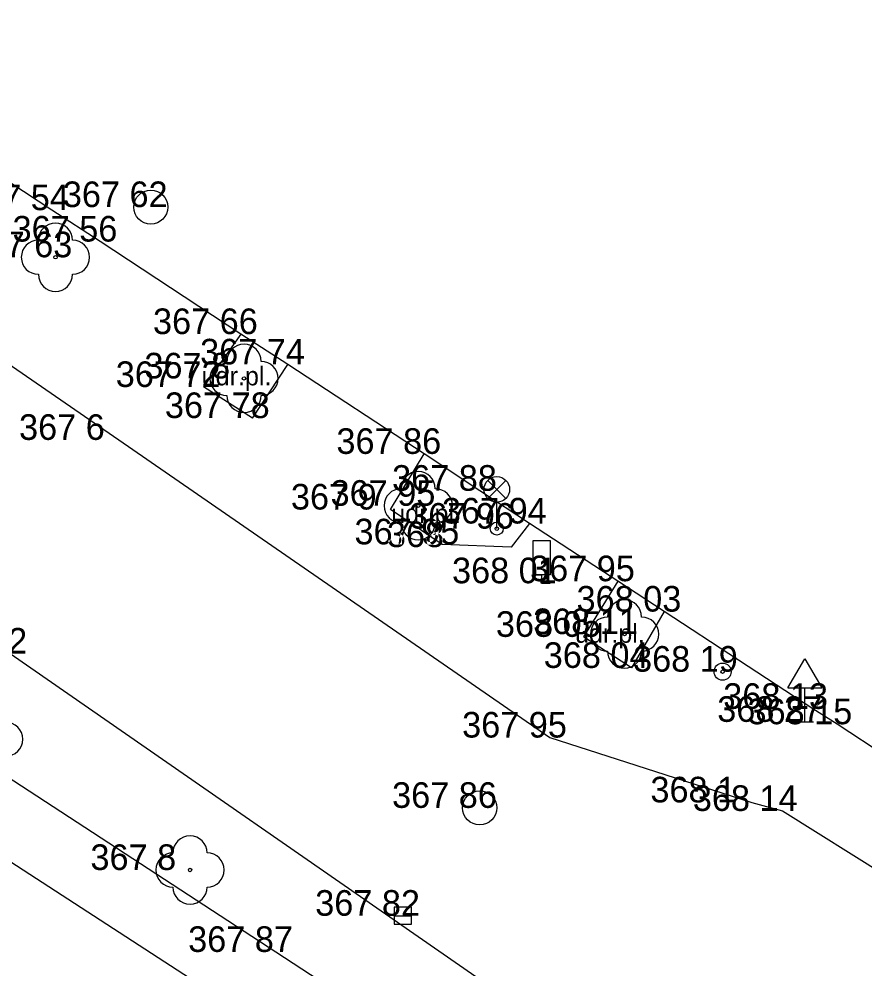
# Model space of a CAD drawing. Extents: x -688316 to -688024, y -973785 to -973591.
# Drawn here: x -688150.19 to -688125.42, y -973669.95 to -973642.12 of the extents above; entities that cross this region are included whole.
import ezdxf

# ---------------------------------------------------------------- set-up
doc = ezdxf.new("R2010")
doc.units = 0
for name, color, linetype in [('Default', 7, 'Continuous'), ('Vrstva 10', 7, 'Continuous'), ('Vrstva 22', 7, 'Continuous'), ('Vrstva 25', 7, 'Continuous'), ('Vrstva 27', 7, 'Continuous'), ('Vrstva 3', 7, 'Continuous'), ('Vrstva 33', 7, 'Continuous'), ('Vrstva 34', 7, 'Continuous'), ('Vrstva 40', 7, 'Continuous'), ('Vrstva 58', 7, 'Continuous')]:
    doc.layers.add(name, color=color, linetype=linetype)

# ---------------------------------------------------------------- blocks, each defined once
blk = doc.blocks.new('DZ')
at = {"layer": 'Vrstva 34'}
for p, q in [((-5, 10), (0, 18.5)), ((0, 18.5), (5, 10)), ((-5, 10), (5, 10)), ((0, 0), (0, 10)), ((-2.49, 0), (2.49, 0))]:
    blk.add_line(p, q, dxfattribs=at)
blk = doc.blocks.new('POINT_DISPLAY')
at = {"layer": 'Default'}
blk.add_line((0, 0), (0, 0), dxfattribs=at)
blk = doc.blocks.new('SKRIN')
at = {"layer": 'Vrstva 58'}
for p, q in [((-2.5, 2.5), (-2.5, 12.5)), ((-2.5, 12.5), (2.5, 12.5)), ((2.5, 12.5), (2.5, 2.5)), ((2.5, 2.5), (-2.5, 2.5)), ((-2.5, 2.5), (0, 2.5)), ((0, 2.5), (0, 0)), ((0, 0), (2.5, 0))]:
    blk.add_line(p, q, dxfattribs=at)
blk.add_blockref('POINT_DISPLAY', (2.5, 2.5), dxfattribs=at)
blk = doc.blocks.new('SAK')
at = {"layer": 'Vrstva 27'}
blk.add_circle((0, 0), 5, dxfattribs=at)
blk = doc.blocks.new('STL')
at = {"layer": 'Vrstva 22'}
blk.add_circle((0, 0), 0.5, dxfattribs=at)
for centre, start, end in [((0, 5), 0, 180), ((-5, 0), 90, 270), ((5, 0), 270, 90), ((0, -5), 180, 0)]:
    blk.add_arc(centre, 5, start, end, dxfattribs=at)
blk = doc.blocks.new('ZKUDR0')
at = {"layer": 'Vrstva 40'}
blk.add_text('udr.pl.', height=5.5, dxfattribs=at).set_placement((-11.71, -3.04))
blk = doc.blocks.new('LA')
at = {"layer": 'Vrstva 33'}
for p, q in [((-2.65, 14.15), (2.65, 8.85)), ((-2.65, 8.85), (2.65, 14.15)), ((0, 0), (0, 7.75))]:
    blk.add_line(p, q, dxfattribs=at)
for centre, radius in [((0, 11.5), 3.75), ((0, 0), 1.9), ((0, 0), 0.5)]:
    blk.add_circle(centre, radius, dxfattribs=at)
blk = doc.blocks.new('VP')
at = {"layer": 'Vrstva 27'}
blk.add_line((-2.5, 0), (2.5, 0), dxfattribs=at)
blk.add_lwpolyline([(-2.5, -2.5), (2.5, -2.5), (2.5, 2.5), (-2.5, 2.5)], close=True, dxfattribs=at)
blk = doc.blocks.new('SPMR')
at = {"layer": 'Vrstva 25'}
for radius in [2.5, 0.5]:
    blk.add_circle((0, 0), radius, dxfattribs=at)

msp = doc.modelspace()

# ---------------------------------------------------------------- linework, layer by layer
at = {"layer": 'Vrstva 10'}
for p, q in [((-688165.13, -973642.12), (-688147.27, -973654.45)), ((-688143.69, -973651.35), (-688144.79, -973652.9)), ((-688143.35, -973653.81), (-688142.32, -973652.24)), ((-688143.35, -973653.81), (-688144.79, -973652.9)), ((-688147.27, -973654.45), (-688134.65, -973663.17)), ((-688139.31, -973656.49), (-688138.33, -973654.86)), ((-688135.24, -973656.9), (-688135.78, -973657.59)), ((-688132.66, -973658.59), (-688133.66, -973660.22)), ((-688131.3, -973659.48), (-688132.26, -973661.13)), ((-688132.26, -973661.13), (-688133.66, -973660.22)), ((-688150.45, -973660.71), (-688131.07, -973674.15)), ((-688126.24, -973662.78), (-688126.95, -973662.33)), ((-688119.64, -973667.13), (-688126.24, -973662.78)), ((-688152.2, -973663.22), (-688142.67, -973669.45)), ((-688134.65, -973663.17), (-688128.73, -973665.07)), ((-688128.73, -973665.07), (-688127.84, -973665.32)), ((-688152.48, -973665.48), (-688142.05, -973672.25)), ((-688127.84, -973665.32), (-688121.4, -973669.35))]:
    msp.add_line(p, q, dxfattribs=at)
for points in [[(-688149.23, -973647.72), (-688153.35, -973645.01), (-688154.77, -973644.07)], [(-688143.69, -973651.35), (-688147.81, -973648.64), (-688149.23, -973647.72)], [(-688138.33, -973654.86), (-688142.32, -973652.24), (-688143.69, -973651.35)], [(-688132.66, -973658.59), (-688135.24, -973656.9), (-688136.7, -973655.94), (-688138.33, -973654.86)], [(-688135.78, -973657.59), (-688137.8, -973657.51), (-688139.31, -973656.49)], [(-688126.95, -973662.33), (-688131.3, -973659.48), (-688132.66, -973658.59)], [(-688142.67, -973669.45), (-688132.43, -973676.15), (-688129.37, -973678.25)]]:
    msp.add_lwpolyline(points, dxfattribs=at)

# ---------------------------------------------------------------- block references
at = {"layer": 'Vrstva 22', "xscale": 0.1, "yscale": 0.10000000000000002}
for p in [(-688149.12, -973649.1), (-688143.6, -973652.65), (-688138.5, -973656.38), (-688132.46, -973660.14), (-688151.08, -973663.22), (-688145.18, -973667.05)]:
    msp.add_blockref('STL', p, dxfattribs=at)
at = {"layer": 'Vrstva 25', "xscale": 0.1, "yscale": 0.10000000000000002}
msp.add_blockref('SPMR', (-688129.59, -973661.24), dxfattribs=at)
at = {"layer": 'Vrstva 27', "xscale": 0.1, "yscale": 0.10000000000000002}
for name, p in [('SAK', (-688146.33, -973647.63)), ('SAK', (-688136.7, -973665.23)), ('VP', (-688138.95, -973668.39))]:
    msp.add_blockref(name, p, dxfattribs=at)
at = {"layer": 'Vrstva 33', "xscale": 0.1, "yscale": 0.10000000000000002}
msp.add_blockref('LA', (-688136.2, -973657.05), dxfattribs=at)
at = {"layer": 'Vrstva 34', "xscale": 0.1, "yscale": 0.10000000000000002}
msp.add_blockref('DZ', (-688127.18, -973662.71), dxfattribs=at)
msp.add_blockref('DZ', (-688127.18, -973662.71), dxfattribs=at)
msp.add_blockref('DZ', (-688127.18, -973662.71), dxfattribs=at)
msp.add_blockref('DZ', (-688127.18, -973662.71), dxfattribs=at)
at = {"layer": 'Vrstva 40', "xscale": 0.1, "yscale": 0.10000000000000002}
for p in [(-688143.67, -973652.55), (-688138.12, -973656.58), (-688132.74, -973660.09)]:
    msp.add_blockref('ZKUDR0', p, dxfattribs=at)
at = {"layer": 'Vrstva 58', "xscale": 0.1, "yscale": 0.10000000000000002}
msp.add_blockref('SKRIN', (-688134.89, -973658.65), dxfattribs=at)
msp.add_blockref('SKRIN', (-688134.89, -973658.65), dxfattribs=at)
msp.add_blockref('SKRIN', (-688134.89, -973658.65), dxfattribs=at)
msp.add_blockref('SKRIN', (-688134.89, -973658.65), dxfattribs=at)

# ---------------------------------------------------------------- texts
at = {"layer": 'Vrstva 3'}
for s, p in [('367 54 ', (-688151.796, -973647.72)), ('367 54 ', (-688151.796, -973647.72)), ('367 54 ', (-688151.796, -973647.72)), ('367 54 ', (-688151.796, -973647.72)), ('367 54 ', (-688151.796, -973647.72)), ('367 54 ', (-688151.796, -973647.72)), ('367 54 ', (-688151.796, -973647.72)), ('367 62 ', (-688148.905, -973647.63)), ('367 62 ', (-688148.905, -973647.63)), ('367 62 ', (-688148.905, -973647.63)), ('367 62 ', (-688148.905, -973647.63)), ('367 62 ', (-688148.905, -973647.63)), ('367 62 ', (-688148.905, -973647.63)), ('367 62 ', (-688148.905, -973647.63)), ('367 56 ', (-688150.376, -973648.64)), ('367 56 ', (-688150.376, -973648.64)), ('367 56 ', (-688150.376, -973648.64)), ('367 56 ', (-688150.376, -973648.64)), ('367 56 ', (-688150.376, -973648.64)), ('367 56 ', (-688150.376, -973648.64)), ('367 56 ', (-688150.376, -973648.64)), ('367 63 ', (-688151.695, -973649.1)), ('367 63 ', (-688151.695, -973649.1)), ('367 63 ', (-688151.695, -973649.1)), ('367 63 ', (-688151.695, -973649.1)), ('367 63 ', (-688151.695, -973649.1)), ('367 63 ', (-688151.695, -973649.1)), ('367 63 ', (-688151.695, -973649.1)), ('367 66 ', (-688146.265, -973651.35)), ('367 66 ', (-688146.265, -973651.35)), ('367 66 ', (-688146.265, -973651.35)), ('367 66 ', (-688146.265, -973651.35)), ('367 66 ', (-688146.265, -973651.35)), ('367 66 ', (-688146.265, -973651.35)), ('367 66 ', (-688146.265, -973651.35)), ('367 74 ', (-688144.886, -973652.24)), ('367 74 ', (-688144.886, -973652.24)), ('367 74 ', (-688144.886, -973652.24)), ('367 74 ', (-688144.886, -973652.24)), ('367 74 ', (-688144.886, -973652.24)), ('367 74 ', (-688144.886, -973652.24)), ('367 74 ', (-688144.886, -973652.24)), ('367 72 ', (-688147.356, -973652.9)), ('367 72 ', (-688147.356, -973652.9)), ('367 72 ', (-688147.356, -973652.9)), ('367 72 ', (-688147.356, -973652.9)), ('367 72 ', (-688147.356, -973652.9)), ('367 72 ', (-688147.356, -973652.9)), ('367 72 ', (-688147.356, -973652.9)), ('367 8  ', (-688146.517, -973652.65)), ('367 8  ', (-688146.517, -973652.65)), ('367 8  ', (-688146.517, -973652.65)), ('367 8  ', (-688146.517, -973652.65)), ('367 8  ', (-688146.517, -973652.65)), ('367 8  ', (-688146.517, -973652.65)), ('367 8  ', (-688146.517, -973652.65)), ('367 78 ', (-688145.916, -973653.81)), ('367 78 ', (-688145.916, -973653.81)), ('367 78 ', (-688145.916, -973653.81)), ('367 78 ', (-688145.916, -973653.81)), ('367 78 ', (-688145.916, -973653.81)), ('367 78 ', (-688145.916, -973653.81)), ('367 78 ', (-688145.916, -973653.81)), ('367 6  ', (-688150.187, -973654.45)), ('367 6  ', (-688150.187, -973654.45)), ('367 6  ', (-688150.187, -973654.45)), ('367 6  ', (-688150.187, -973654.45)), ('367 6  ', (-688150.187, -973654.45)), ('367 6  ', (-688150.187, -973654.45)), ('367 6  ', (-688150.187, -973654.45)), ('367 86 ', (-688140.896, -973654.86)), ('367 86 ', (-688140.896, -973654.86)), ('367 86 ', (-688140.896, -973654.86)), ('367 86 ', (-688140.896, -973654.86)), ('367 86 ', (-688140.896, -973654.86)), ('367 86 ', (-688140.896, -973654.86)), ('367 86 ', (-688140.896, -973654.86)), ('367 88 ', (-688139.266, -973655.94)), ('367 88 ', (-688139.266, -973655.94)), ('367 88 ', (-688139.266, -973655.94)), ('367 88 ', (-688139.266, -973655.94)), ('367 88 ', (-688139.266, -973655.94)), ('367 88 ', (-688139.266, -973655.94)), ('367 88 ', (-688139.266, -973655.94)), ('367 9  ', (-688142.227, -973656.49)), ('367 9  ', (-688142.227, -973656.49)), ('367 9  ', (-688142.227, -973656.49)), ('367 9  ', (-688142.227, -973656.49)), ('367 9  ', (-688142.227, -973656.49)), ('367 9  ', (-688142.227, -973656.49)), ('367 9  ', (-688142.227, -973656.49)), ('367 95 ', (-688141.066, -973656.38)), ('367 95 ', (-688141.066, -973656.38)), ('367 95 ', (-688141.066, -973656.38)), ('367 95 ', (-688141.066, -973656.38)), ('367 95 ', (-688141.066, -973656.38)), ('367 95 ', (-688141.066, -973656.38)), ('367 95 ', (-688141.066, -973656.38)), ('367 96 ', (-688138.766, -973657.05)), ('367 96 ', (-688138.766, -973657.05)), ('367 96 ', (-688138.766, -973657.05)), ('367 96 ', (-688138.766, -973657.05)), ('367 96 ', (-688138.766, -973657.05)), ('367 96 ', (-688138.766, -973657.05)), ('367 96 ', (-688138.766, -973657.05)), ('367 94 ', (-688137.806, -973656.9)), ('367 94 ', (-688137.806, -973656.9)), ('367 94 ', (-688137.806, -973656.9)), ('367 94 ', (-688137.806, -973656.9)), ('367 94 ', (-688137.806, -973656.9)), ('367 94 ', (-688137.806, -973656.9)), ('367 94 ', (-688137.806, -973656.9)), ('367 95 ', (-688140.366, -973657.51)), ('367 95 ', (-688140.366, -973657.51)), ('367 95 ', (-688140.366, -973657.51)), ('367 95 ', (-688140.366, -973657.51)), ('367 95 ', (-688140.366, -973657.51)), ('367 95 ', (-688140.366, -973657.51)), ('367 95 ', (-688140.366, -973657.51)), ('368    ', (-688139.417, -973657.59)), ('368    ', (-688139.417, -973657.59)), ('368    ', (-688139.417, -973657.59)), ('368    ', (-688139.417, -973657.59)), ('368    ', (-688139.417, -973657.59)), ('368    ', (-688139.417, -973657.59)), ('368    ', (-688139.417, -973657.59)), ('368 01 ', (-688137.511, -973658.65)), ('368 01 ', (-688137.511, -973658.65)), ('368 01 ', (-688137.511, -973658.65)), ('368 01 ', (-688137.511, -973658.65)), ('368 01 ', (-688137.511, -973658.65)), ('368 01 ', (-688137.511, -973658.65)), ('368 01 ', (-688137.511, -973658.65)), ('367 95 ', (-688135.226, -973658.59)), ('367 95 ', (-688135.226, -973658.59)), ('367 95 ', (-688135.226, -973658.59)), ('367 95 ', (-688135.226, -973658.59)), ('367 95 ', (-688135.226, -973658.59)), ('367 95 ', (-688135.226, -973658.59)), ('367 95 ', (-688135.226, -973658.59)), ('368 03 ', (-688133.866, -973659.48)), ('368 03 ', (-688133.866, -973659.48)), ('368 03 ', (-688133.866, -973659.48)), ('368 03 ', (-688133.866, -973659.48)), ('368 03 ', (-688133.866, -973659.48)), ('368 03 ', (-688133.866, -973659.48)), ('368 03 ', (-688133.866, -973659.48)), ('368 11 ', (-688135.137, -973660.14)), ('368 11 ', (-688135.137, -973660.14)), ('368 11 ', (-688135.137, -973660.14)), ('368 11 ', (-688135.137, -973660.14)), ('368 11 ', (-688135.137, -973660.14)), ('368 11 ', (-688135.137, -973660.14)), ('368 11 ', (-688135.137, -973660.14)), ('368 05 ', (-688136.226, -973660.22)), ('368 05 ', (-688136.226, -973660.22)), ('368 05 ', (-688136.226, -973660.22)), ('368 05 ', (-688136.226, -973660.22)), ('368 05 ', (-688136.226, -973660.22)), ('368 05 ', (-688136.226, -973660.22)), ('368 05 ', (-688136.226, -973660.22)), ('367 52 ', (-688153.016, -973660.71)), ('367 52 ', (-688153.016, -973660.71)), ('367 52 ', (-688153.016, -973660.71)), ('367 52 ', (-688153.016, -973660.71)), ('367 52 ', (-688153.016, -973660.71)), ('367 52 ', (-688153.016, -973660.71)), ('367 52 ', (-688153.016, -973660.71)), ('368 04 ', (-688134.826, -973661.13)), ('368 04 ', (-688134.826, -973661.13)), ('368 04 ', (-688134.826, -973661.13)), ('368 04 ', (-688134.826, -973661.13)), ('368 04 ', (-688134.826, -973661.13)), ('368 04 ', (-688134.826, -973661.13)), ('368 04 ', (-688134.826, -973661.13)), ('368 19 ', (-688132.211, -973661.24)), ('368 19 ', (-688132.211, -973661.24)), ('368 19 ', (-688132.211, -973661.24)), ('368 19 ', (-688132.211, -973661.24)), ('368 19 ', (-688132.211, -973661.24)), ('368 19 ', (-688132.211, -973661.24)), ('368 19 ', (-688132.211, -973661.24)), ('368 13 ', (-688129.571, -973662.33)), ('368 13 ', (-688129.571, -973662.33)), ('368 13 ', (-688129.571, -973662.33)), ('368 13 ', (-688129.571, -973662.33)), ('368 13 ', (-688129.571, -973662.33)), ('368 13 ', (-688129.571, -973662.33)), ('368 13 ', (-688129.571, -973662.33)), ('368 27 ', (-688129.746, -973662.71)), ('368 27 ', (-688129.746, -973662.71)), ('368 27 ', (-688129.746, -973662.71)), ('368 27 ', (-688129.746, -973662.71)), ('368 27 ', (-688129.746, -973662.71)), ('368 27 ', (-688129.746, -973662.71)), ('368 27 ', (-688129.746, -973662.71)), ('368 15 ', (-688128.861, -973662.78)), ('368 15 ', (-688128.861, -973662.78)), ('368 15 ', (-688128.861, -973662.78)), ('368 15 ', (-688128.861, -973662.78)), ('368 15 ', (-688128.861, -973662.78)), ('368 15 ', (-688128.861, -973662.78)), ('368 15 ', (-688128.861, -973662.78)), ('367 95 ', (-688137.216, -973663.17)), ('367 95 ', (-688137.216, -973663.17)), ('367 95 ', (-688137.216, -973663.17)), ('367 95 ', (-688137.216, -973663.17)), ('367 95 ', (-688137.216, -973663.17)), ('367 95 ', (-688137.216, -973663.17)), ('367 95 ', (-688137.216, -973663.17)), ('368 1  ', (-688131.703, -973665.07)), ('368 1  ', (-688131.703, -973665.07)), ('368 1  ', (-688131.703, -973665.07)), ('368 1  ', (-688131.703, -973665.07)), ('368 1  ', (-688131.703, -973665.07)), ('368 1  ', (-688131.703, -973665.07)), ('368 1  ', (-688131.703, -973665.07)), ('367 86 ', (-688139.266, -973665.23)), ('367 86 ', (-688139.266, -973665.23)), ('367 86 ', (-688139.266, -973665.23)), ('367 86 ', (-688139.266, -973665.23)), ('367 86 ', (-688139.266, -973665.23)), ('367 86 ', (-688139.266, -973665.23)), ('367 86 ', (-688139.266, -973665.23)), ('368 14 ', (-688130.461, -973665.32)), ('368 14 ', (-688130.461, -973665.32)), ('368 14 ', (-688130.461, -973665.32)), ('368 14 ', (-688130.461, -973665.32)), ('368 14 ', (-688130.461, -973665.32)), ('368 14 ', (-688130.461, -973665.32)), ('368 14 ', (-688130.461, -973665.32)), ('367 8  ', (-688148.097, -973667.05)), ('367 8  ', (-688148.097, -973667.05)), ('367 8  ', (-688148.097, -973667.05)), ('367 8  ', (-688148.097, -973667.05)), ('367 8  ', (-688148.097, -973667.05)), ('367 8  ', (-688148.097, -973667.05)), ('367 8  ', (-688148.097, -973667.05)), ('367 82 ', (-688141.516, -973668.39)), ('367 82 ', (-688141.516, -973668.39)), ('367 82 ', (-688141.516, -973668.39)), ('367 82 ', (-688141.516, -973668.39)), ('367 82 ', (-688141.516, -973668.39)), ('367 82 ', (-688141.516, -973668.39)), ('367 82 ', (-688141.516, -973668.39)), ('367 87 ', (-688145.236, -973669.45)), ('367 87 ', (-688145.236, -973669.45)), ('367 87 ', (-688145.236, -973669.45)), ('367 87 ', (-688145.236, -973669.45)), ('367 87 ', (-688145.236, -973669.45)), ('367 87 ', (-688145.236, -973669.45)), ('367 87 ', (-688145.236, -973669.45))]:
    msp.add_text(s, height=0.75, dxfattribs=at).set_placement(p)

doc.saveas('drawing.dxf')
